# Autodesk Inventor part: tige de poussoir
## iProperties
Author: chr
Created: 2002-03
Part Number: tige de poussoir
Material: Par défaut
Document SubType Name: Modélisation
Designer: chr
Control State: 0
Master: False
Checked Out: False
PropertySet Name: Design Tracking Control
Shininess: 20.0
Angle Display Precision: 2
Document Length Units: 11269
Document Angle Units: 11283
Document Time Units: 11279
Document Mass Units: 11290
Document Length Units Precision: 3
Document Angle Units Precision: 2
Compacted: False
PropertySet Name: _Private Model Information
Density: 0.0
Volumn: 0.0
Area: 0.0
PropertySet Name: Model Information
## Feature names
1. Révolution1 [Revolution]
